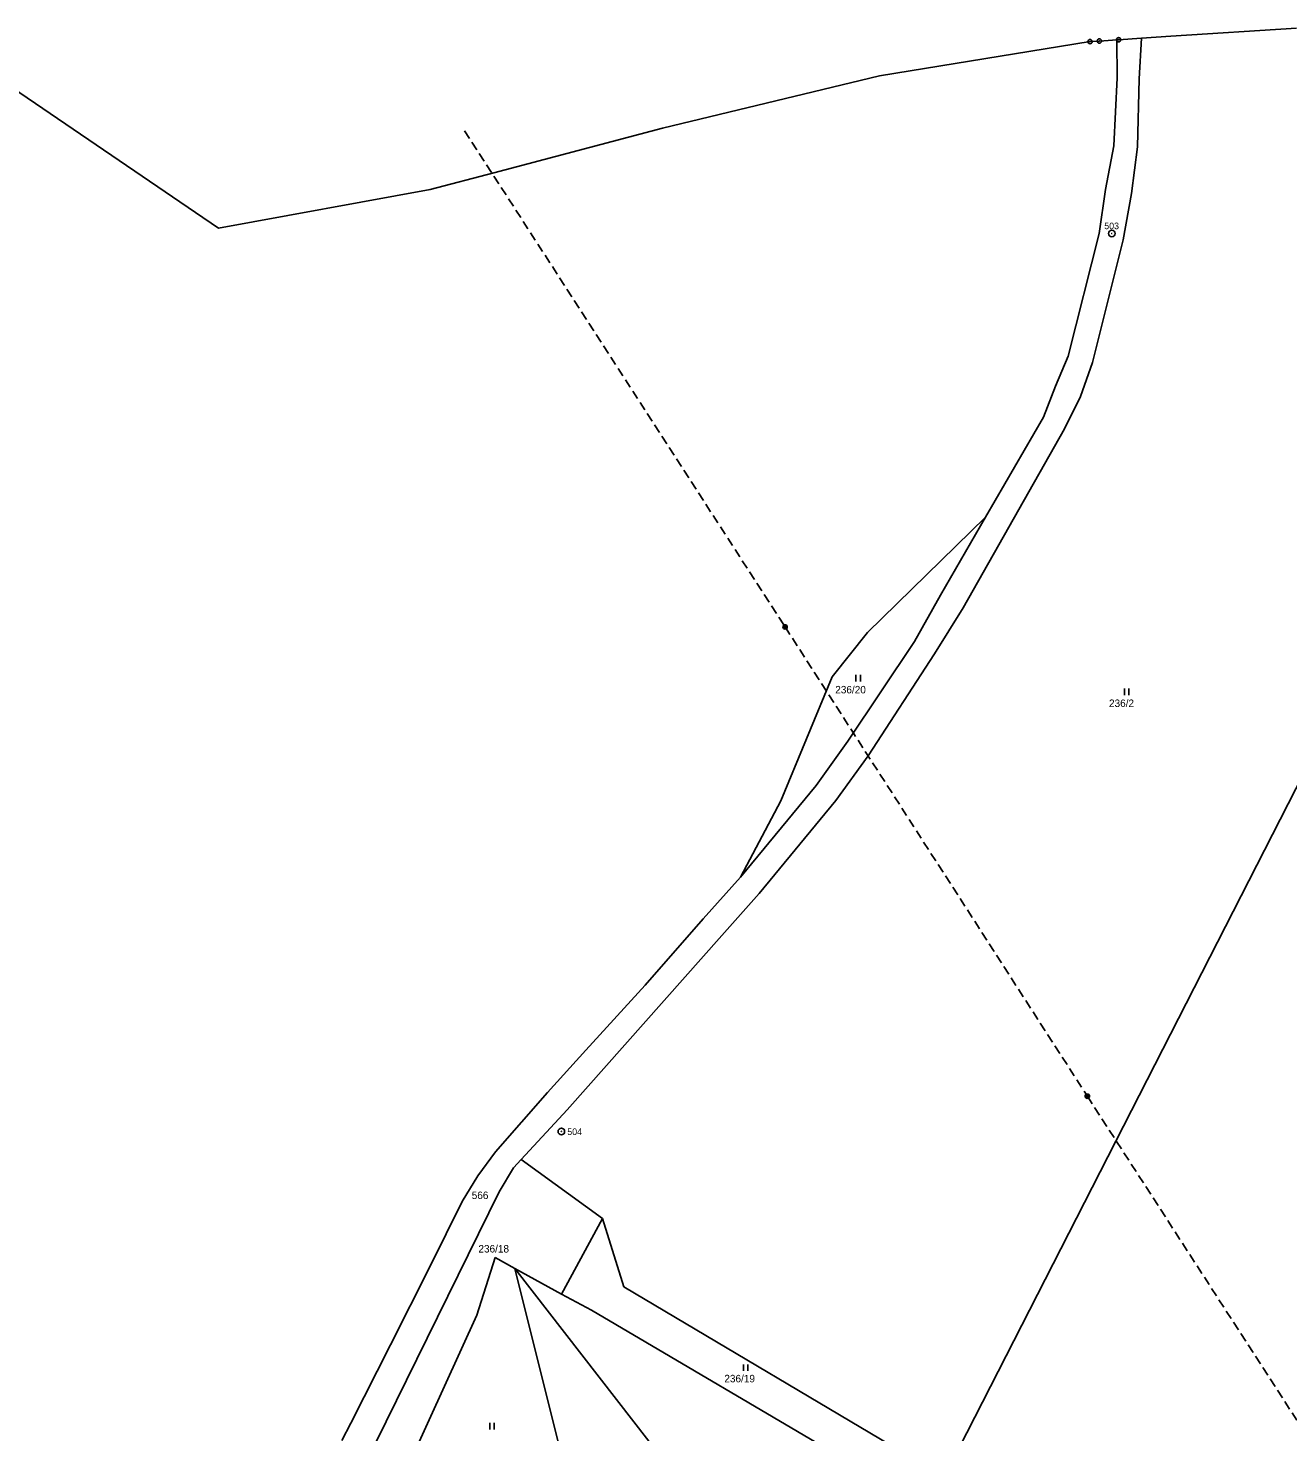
# Model space of a CAD drawing. Extents: x -885985 to -883535, y -1030025 to -1027941.
# Drawn here: x -884708.9 to -884422.7, y -1028299.8 to -1027980.8 of the extents above; entities that cross this region are included whole.
import ezdxf
from ezdxf.enums import TextEntityAlignment as Align

# ---------------------------------------------------------------- set-up
doc = ezdxf.new("R2010")
doc.units = 0
doc.header["$LTSCALE"] = 0.68
doc.linetypes.add('MEDIUM_DASHED', pattern=[4.5, 3, -1.5])
for name, color, linetype, lineweight in [('1', 7, 'Continuous', 25), ('3', 7, 'Continuous', 25), ('6', 7, 'Continuous', 25), ('8', 7, 'Continuous', 25)]:
    doc.layers.add(name, color=color, linetype=linetype, lineweight=lineweight)
doc.layers.add('2', color=7, linetype='Continuous')

msp = doc.modelspace()

# ---------------------------------------------------------------- linework, layer by layer
at = {"layer": '1'}
for p, q in [((-884465.51, -1027983.73), (-884467.63, -1027983.87)), ((-884461.56, -1027983.47), (-884465.51, -1027983.73)), ((-884461.15, -1027983.44), (-884461.56, -1027983.47)), ((-884461.56, -1027983.47), (-884461.51, -1027992.1)), ((-884461.15, -1027983.44), (-884455.95, -1027983.1)), ((-884456.47, -1027992.32), (-884455.95, -1027983.1)), ((-884455.95, -1027983.1), (-884449.28, -1027982.66)), ((-884420.75, -1027980.79), (-884449.28, -1027982.66)), ((-884727, -1027984.46), (-884665.7, -1028026.3)), ((-884467.63, -1027983.87), (-884515.47, -1027991.64)), ((-884515.47, -1027991.64), (-884564.79, -1028003.56)), ((-884461.51, -1027992.1), (-884462.2, -1028007.53)), ((-884456.84, -1028007.76), (-884456.47, -1027992.32)), ((-884564.79, -1028003.56), (-884603.12, -1028013.7)), ((-884462.2, -1028007.53), (-884464.13, -1028017.48)), ((-884458.25, -1028018.37), (-884456.84, -1028007.76)), ((-884603.12, -1028013.7), (-884617.54, -1028017.51)), ((-884617.54, -1028017.51), (-884665.7, -1028026.3)), ((-884464.13, -1028017.48), (-884465.6, -1028027.47)), ((-884460.14, -1028028.88), (-884458.25, -1028018.37)), ((-884465.6, -1028027.47), (-884472.58, -1028055.37)), ((-884467.08, -1028056.8), (-884460.14, -1028028.88)), ((-884472.58, -1028055.37), (-884475.51, -1028062.18)), ((-884469.78, -1028064.5), (-884467.08, -1028056.8)), ((-884475.51, -1028062.18), (-884478.19, -1028069.18)), ((-884473.46, -1028071.87), (-884469.78, -1028064.5)), ((-884478.19, -1028069.18), (-884491.4, -1028091.98)), ((-884496.46, -1028112.57), (-884473.46, -1028071.87)), ((-884491.4, -1028091.98), (-884518.24, -1028118.19)), ((-884491.4, -1028091.98), (-884501.63, -1028109.64)), ((-884501.63, -1028109.64), (-884507.51, -1028120.22)), ((-884502.99, -1028122.98), (-884496.46, -1028112.57)), ((-884518.24, -1028118.19), (-884526.21, -1028128.23)), ((-884507.51, -1028120.22), (-884522.66, -1028142.86)), ((-884518.05, -1028146.16), (-884502.99, -1028122.98)), ((-884526.21, -1028128.23), (-884537.89, -1028156.41)), ((-884522.66, -1028142.86), (-884529.89, -1028152.9)), ((-884414.76, -1028141.6), (-884500.76, -1028310.05)), ((-884525.38, -1028156.36), (-884518.05, -1028146.16)), ((-884529.89, -1028152.9), (-884547.04, -1028173.74)), ((-884537.89, -1028156.41), (-884547.04, -1028173.74)), ((-884542.85, -1028177.45), (-884525.38, -1028156.36)), ((-884547.04, -1028173.74), (-884555.54, -1028183.26)), ((-884551.27, -1028187.05), (-884542.85, -1028177.45)), ((-884555.54, -1028183.26), (-884568.75, -1028198.28)), ((-884586.44, -1028226.66), (-884551.27, -1028187.05)), ((-884568.75, -1028198.28), (-884582.21, -1028213.07)), ((-884582.21, -1028213.07), (-884590.9, -1028222.71)), ((-884590.9, -1028222.71), (-884602.72, -1028236.15)), ((-884596.88, -1028237.93), (-884586.44, -1028226.66)), ((-884602.72, -1028236.15), (-884606.75, -1028241.66)), ((-884596.88, -1028237.93), (-884598.61, -1028239.8)), ((-884578.45, -1028251.34), (-884596.88, -1028237.93)), ((-884606.75, -1028241.66), (-884610.33, -1028247.47)), ((-884598.61, -1028239.8), (-884601.9, -1028245.3)), ((-884601.9, -1028245.3), (-884640.99, -1028324.69)), ((-884610.33, -1028247.47), (-884617.58, -1028262.16)), ((-884578.45, -1028251.34), (-884587.7, -1028268.51)), ((-884573.54, -1028266.88), (-884578.45, -1028251.34)), ((-884602.83, -1028260.23), (-884606.99, -1028273.29)), ((-884598.34, -1028262.73), (-884602.83, -1028260.23)), ((-884617.58, -1028262.16), (-884626.57, -1028280.03)), ((-884587.7, -1028268.51), (-884598.34, -1028262.73)), ((-884598.34, -1028262.73), (-884542.88, -1028334.03)), ((-884598.34, -1028262.73), (-884583.43, -1028322.24)), ((-884500.76, -1028310.05), (-884573.54, -1028266.88)), ((-884580.94, -1028272.18), (-884587.7, -1028268.51)), ((-884606.99, -1028273.29), (-884621.63, -1028305.56)), ((-884512.54, -1028312.41), (-884580.94, -1028272.18)), ((-884626.57, -1028280.03), (-884635.61, -1028297.86)), ((-884635.61, -1028297.86), (-884637.65, -1028301.77))]:
    msp.add_line(p, q, dxfattribs=at)
at = {"layer": '3'}
for p, q in [((-884520.821, -1028129.27), (-884520.821, -1028127.77)), ((-884519.82, -1028129.27), (-884519.82, -1028127.77)), ((-884459.791, -1028132.42), (-884459.791, -1028130.92)), ((-884458.79, -1028132.42), (-884458.79, -1028130.92)), ((-884546.361, -1028285.98), (-884546.361, -1028284.48)), ((-884545.36, -1028285.98), (-884545.36, -1028284.48)), ((-884604.001, -1028299.3), (-884604.001, -1028297.8)), ((-884603, -1028299.3), (-884603, -1028297.8))]:
    msp.add_line(p, q, dxfattribs=at)
at = {"layer": '6', "linetype": 'MEDIUM_DASHED'}
for p, q in [((-884609.74, -1028004.16), (-884536.92, -1028116.89)), ((-884536.92, -1028116.89), (-884468.25, -1028223.54)), ((-884468.25, -1028223.54), (-884397.9, -1028332.33))]:
    msp.add_line(p, q, dxfattribs=at)
at = {"layer": '6'}
for centre, radius in [((-884536.9234, -1028116.8899), 0.5), ((-884536.9234, -1028116.8899), 0.4), ((-884536.9234, -1028116.8899), 0.3), ((-884536.9234, -1028116.8899), 0.2), ((-884536.9234, -1028116.8899), 0.1), ((-884468.2534, -1028223.5399), 0.5), ((-884468.2534, -1028223.5399), 0.4), ((-884468.2534, -1028223.5399), 0.3), ((-884468.2534, -1028223.5399), 0.2), ((-884468.2534, -1028223.5399), 0.1)]:
    msp.add_circle(centre, radius, dxfattribs=at)
at = {"layer": '8'}
for centre, radius in [((-884467.63, -1027983.8699), 0.5), ((-884465.51, -1027983.7299), 0.5), ((-884465.51, -1027983.7299), 0.0303), ((-884461.15, -1027983.4399), 0.5), ((-884461.15, -1027983.4399), 0.0303), ((-884467.63, -1027983.8699), 0.0303), ((-884462.7, -1028027.4798), 0.75), ((-884462.7, -1028027.4798), 0.03), ((-884587.77, -1028231.5398), 0.75), ((-884587.77, -1028231.5398), 0.03)]:
    msp.add_circle(centre, radius, dxfattribs=at)

# ---------------------------------------------------------------- texts
at = {"layer": '2'}
for s, p in [('236/20', (-884525.53, -1028131.995)), ('236/2', (-884463.33, -1028135.085)), ('566', (-884608.13, -1028246.915)), ('236/18', (-884606.61, -1028259.065)), ('236/19', (-884550.73, -1028288.565))]:
    msp.add_text(s, height=1.7, dxfattribs=at).set_placement(p)
at = {"layer": '8'}
for s, p in [('503', (-884461.06, -1028026.495)), ('504', (-884583.07, -1028232.362))]:
    msp.add_text(s, height=1.5, dxfattribs=at).set_placement(p, align=Align.RIGHT)

doc.saveas('drawing.dxf')
